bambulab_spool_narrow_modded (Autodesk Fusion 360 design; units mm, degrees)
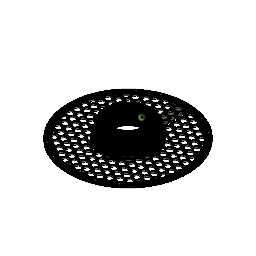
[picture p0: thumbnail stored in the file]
parameter "hole_distance_from_top" = 12.75
parameter "hole_distance_from_sides" = 32
parameter "lattice_thickness" = 3.75
parameter "lattice_diameter" = 10.25
base_mesh_feature "Base Mesh Feature"
convert_mesh "Convert Mesh"
sketch "Sketch1" plane through (0, 0, -13.45) normal (0, 0, 1) x axis (-1, 0, 0)
  line L1 (91.1991, -17.1626) -> (97.9893, -17.84)
  line L2 (90.8249, -19.0441) -> (91.1991, -17.1626)
  line L3 (97.9893, -17.84) -> (90.8249, -19.0441)
  circle C1 centre (94.8184, -14.9969) radius 1.75
  circle C2 centre (94.8205, 15.0016) radius 1.75
  circle C3 centre (60.3969, 74.6167) radius 1.75
  circle C4 centre (-34.4215, 89.6136) radius 1.75
  circle C5 centre (-94.8184, 14.9969) radius 1.75
  circle C6 centre (-60.3969, -74.6167) radius 1.75
  circle C7 centre (34.4215, -89.6136) radius 1.75
  circle C8 centre (34.4185, 89.6178) radius 1.75
  circle C9 centre (-60.402, 74.6162) radius 1.75
  circle C10 centre (-94.8205, -15.0016) radius 1.75
  circle C11 centre (-34.4185, -89.6178) radius 1.75
  circle C12 centre (60.402, -74.6162) radius 1.75
  point P1 (0, 0)
  point P7 (0, 0)
  coincident P1 P7
  dimension "d1" diameter C2 = 3.5
  dimension "d2" diameter C1 = 3.5
  dimension "d4" C-Pattern1-Angle = 360
  dimension "d6" C-Pattern2-Angle = 360
extrude "Extrude1" cut sketch "Sketch1" profile of C3 C4 C6 C7 C8 C9 C11 C12 against normal blind 11
sketch "Sketch2" plane through (0, 0, 0) normal (1, 0, 0) x axis (0, 1, 0)
  line L1 (0, -25) -> (0, 24)
  line L2 (-63, 0) -> (50, 0)
  circle C1 centre (-32, -12.75) radius 1.1
  circle C2 centre (32, -12.75) radius 1.1
  point P2 (-32, -12.75)
  point P3 (32, -12.75)
  vertical L1
  horizontal L2
  dimension "d9" diameter C2 = 2.2
  dimension "d10" diameter C1 = 2.2
  dimension "d11" distance P2 L1 = 32 (= "hole_distance_from_sides")
  dimension "d12" distance P3 L1 = 32 (= "hole_distance_from_sides")
  dimension "d13" distance P3 L2 = 12.75 (= "hole_distance_from_top")
  dimension "d16" distance P2 L2 = 12.75 (= "hole_distance_from_top")
work_plane "WorkPlane1" AlongDistance -61
work_plane "WorkPlane2" AlongDistance -64
work_plane "WorkPlane3" AlongDistance 64
work_plane "WorkPlane4" AlongDistance 65
sketch "Sketch3" plane through (64, 0, 0) normal (1, 0, 0) x axis (0, 1, 0)
  circle C1 centre (-32, -12.75) radius 1.1
  circle C2 centre (32, -12.75) radius 1.1
extrude "Extrude2" cut sketch "Sketch3" against normal blind 57
sketch "Sketch4" plane through (-61, 0, 0) normal (1, 0, 0) x axis (0, 1, 0)
  circle C1 centre (32, -12.75) radius 1.1
  circle C2 centre (-32, -12.75) radius 1.1
extrude "Extrude3" cut sketch "Sketch4" along normal blind 56
sketch "Sketch5" plane through (0, 65, 0) normal (0, 1, 0) x axis (1, 0, 0)
  line L1 (0, 26) -> (0, -23)
  line L2 (-49.4611, 0) -> (56, 0)
  circle C1 centre (32, 12.75) radius 1.1
  circle C2 centre (-32, 12.75) radius 1.1
  point P7 (-32, 12.75)
  point P6 (32, 12.75)
  vertical L1
  horizontal L2
  dimension "d25" diameter C1 = 2.2
  dimension "d26" diameter C2 = 2.2
  dimension "d27" distance L2 P7 = 12.75 (= "hole_distance_from_top")
  dimension "d28" distance L2 P6 = 12.75 (= "hole_distance_from_top")
  dimension "d29" distance L1 P6 = 32 (= "hole_distance_from_sides")
  dimension "d30" distance L1 P7 = 32 (= "hole_distance_from_sides")
extrude "Extrude4" cut sketch "Sketch5" profile of C1 C2 against normal blind 60
sketch "Sketch6" plane through (0, -64, 0) normal (0, 1, 0) x axis (1, 0, 0)
  circle C1 centre (32, 12.75) radius 1.1
  circle C2 centre (-32, 12.75) radius 1.1
extrude "Extrude5" cut sketch "Sketch6" along normal blind 60
sketch "Label" plane through (0, 0, -17.05) normal (0, 0, -1) x axis (1, 0, 0)
  line L1 (-1.2532, -46.0788) -> (-0.6281, -46.0197)
  line L2 (-1.8735, -46.1771) -> (-1.2532, -46.0788)
  line L3 (-2.4873, -46.3143) -> (-1.8735, -46.1771)
  line L4 (-3.0901, -46.4894) -> (-2.4873, -46.3143)
  line L5 (-3.6808, -46.7021) -> (-3.0901, -46.4894)
  line L6 (-0.6281, -46.0197) -> (0, -46.0001)
  line L7 (0.6281, -46.0197) -> (0, -46.0001)
  line L8 (1.2532, -46.0788) -> (0.6281, -46.0197)
  line L9 (1.8735, -46.1771) -> (1.2532, -46.0788)
  line L10 (2.4872, -46.3143) -> (1.8735, -46.1771)
  line L11 (3.0901, -46.4894) -> (2.4872, -46.3143)
  line L12 (3.6808, -46.7021) -> (3.0901, -46.4894)
  line L13 (4.2582, -46.9519) -> (3.6808, -46.7021)
  line L14 (4.8175, -47.2369) -> (4.2582, -46.9519)
  line L15 (5.3579, -47.5565) -> (4.8175, -47.2369)
  line L16 (5.878, -47.91) -> (5.3579, -47.5565)
  line L17 (6.3742, -48.2949) -> (5.878, -47.91)
  line L18 (6.8453, -48.7102) -> (6.3742, -48.2949)
  line L19 (7.2897, -49.1546) -> (6.8453, -48.7102)
  line L20 (7.7051, -49.6258) -> (7.2897, -49.1546)
  line L21 (8.0901, -50.1221) -> (7.7051, -49.6258)
  line L22 (8.4431, -50.6416) -> (8.0901, -50.1221)
  line L23 (8.7631, -51.1825) -> (8.4431, -50.6416)
  line L24 (9.0483, -51.7422) -> (8.7631, -51.1825)
  line L25 (9.2976, -52.3185) -> (9.0483, -51.7422)
  line L26 (9.5106, -52.91) -> (9.2976, -52.3185)
  line L27 (9.6858, -53.5131) -> (9.5106, -52.91)
  line L28 (9.8228, -54.1259) -> (9.6858, -53.5131)
  line L29 (9.9212, -54.7468) -> (9.8228, -54.1259)
  line L30 (9.9802, -55.3716) -> (9.9212, -54.7468)
  line L31 (10, -56) -> (9.9802, -55.3716)
  line L32 (10, -82) -> (10, -56)
  line L33 (-9.2976, -52.3185) -> (-9.0483, -51.7422)
  line L34 (-9.0483, -51.7422) -> (-8.7631, -51.1825)
  line L35 (-8.7631, -51.1825) -> (-8.4431, -50.6416)
  line L36 (-8.4431, -50.6416) -> (-8.0901, -50.1221)
  line L37 (-8.0901, -50.1221) -> (-7.7051, -49.6258)
  line L38 (-7.7051, -49.6258) -> (-7.2897, -49.1546)
  line L39 (-7.2897, -49.1546) -> (-6.8453, -48.7102)
  line L40 (-6.8453, -48.7102) -> (-6.3742, -48.2949)
  line L41 (-6.3742, -48.2949) -> (-5.878, -47.91)
  line L42 (-5.878, -47.91) -> (-5.3579, -47.5565)
  line L43 (-5.3579, -47.5565) -> (-4.8175, -47.2369)
  line L44 (-4.8175, -47.2369) -> (-4.2582, -46.9519)
  line L45 (-4.2582, -46.9519) -> (-3.6808, -46.7021)
  line L46 (-9.5106, -52.91) -> (-9.2976, -52.3185)
  line L47 (-9.6858, -53.5131) -> (-9.5106, -52.91)
  line L48 (-9.8228, -54.1259) -> (-9.6858, -53.5131)
  line L49 (-9.9212, -54.7468) -> (-9.8228, -54.1259)
  line L50 (-9.9802, -55.3716) -> (-9.9212, -54.7468)
  line L51 (-10, -56) -> (-9.9802, -55.3716)
  line L52 (-10, -82) -> (-10, -56)
  line L53 (9.9802, -82.6284) -> (10, -82)
  line L54 (9.9212, -83.2532) -> (9.9802, -82.6284)
  line L55 (9.8228, -83.8741) -> (9.9212, -83.2532)
  line L56 (9.6858, -84.4869) -> (9.8228, -83.8741)
  line L57 (9.5106, -85.09) -> (9.6858, -84.4869)
  line L58 (9.2976, -85.6815) -> (9.5106, -85.09)
  line L59 (9.0483, -86.2578) -> (9.2976, -85.6815)
  line L60 (8.7631, -86.8175) -> (9.0483, -86.2578)
  line L61 (8.4431, -87.3584) -> (8.7631, -86.8175)
  line L62 (8.0901, -87.8779) -> (8.4431, -87.3584)
  line L63 (7.7051, -88.3742) -> (8.0901, -87.8779)
  line L64 (7.2897, -88.8454) -> (7.7051, -88.3742)
  line L65 (6.8453, -89.2898) -> (7.2897, -88.8454)
  line L66 (6.3742, -89.7051) -> (6.8453, -89.2898)
  line L67 (5.878, -90.09) -> (6.3742, -89.7051)
  line L68 (5.3579, -90.4435) -> (5.878, -90.09)
  line L69 (4.8175, -90.7631) -> (5.3579, -90.4435)
  line L70 (4.2582, -91.0481) -> (4.8175, -90.7631)
  line L71 (3.6808, -91.2979) -> (4.2582, -91.0481)
  line L72 (3.0901, -91.5106) -> (3.6808, -91.2979)
  line L73 (2.4872, -91.6857) -> (3.0901, -91.5106)
  line L74 (1.8735, -91.8229) -> (2.4872, -91.6857)
  line L75 (1.2532, -91.9212) -> (1.8735, -91.8229)
  line L76 (0.6281, -91.9803) -> (1.2532, -91.9212)
  line L77 (0, -92) -> (0.6281, -91.9803)
  line L78 (0, -92) -> (-0.6281, -91.9803)
  line L79 (-0.6281, -91.9803) -> (-1.2532, -91.9212)
  line L80 (-1.2532, -91.9212) -> (-1.8735, -91.8229)
  line L81 (-1.8735, -91.8229) -> (-2.4873, -91.6857)
  line L82 (-2.4873, -91.6857) -> (-3.0901, -91.5106)
  line L83 (-3.0901, -91.5106) -> (-3.6808, -91.2979)
  line L84 (-3.6808, -91.2979) -> (-4.2582, -91.0481)
  line L85 (-4.2582, -91.0481) -> (-4.8175, -90.7631)
  line L86 (-4.8175, -90.7631) -> (-5.3579, -90.4435)
  line L87 (-5.3579, -90.4435) -> (-5.878, -90.09)
  line L88 (-5.878, -90.09) -> (-6.3742, -89.7051)
  line L89 (-6.3742, -89.7051) -> (-6.8453, -89.2898)
  line L90 (-6.8453, -89.2898) -> (-7.2897, -88.8454)
  line L91 (-7.2897, -88.8454) -> (-7.7051, -88.3742)
  line L92 (-7.7051, -88.3742) -> (-8.0901, -87.8779)
  line L93 (-8.0901, -87.8779) -> (-8.4431, -87.3584)
  line L94 (-8.4431, -87.3584) -> (-8.7631, -86.8175)
  line L95 (-8.7631, -86.8175) -> (-9.0483, -86.2578)
  line L96 (-9.0483, -86.2578) -> (-9.2976, -85.6815)
  line L97 (-9.2976, -85.6815) -> (-9.5106, -85.09)
  line L98 (-9.5106, -85.09) -> (-9.6858, -84.4869)
  line L99 (-9.6858, -84.4869) -> (-9.8228, -83.8741)
  line L100 (-9.8228, -83.8741) -> (-9.9212, -83.2532)
  line L101 (-9.9212, -83.2532) -> (-9.9802, -82.6284)
  line L102 (-9.9802, -82.6284) -> (-10, -82)
  line L103 (-10.3182, -83.3033) -> (-10.3796, -82.6536)
  line L104 (-10.2159, -83.9491) -> (-10.3182, -83.3033)
  line L105 (-10.0734, -84.5864) -> (-10.2159, -83.9491)
  line L106 (-9.8912, -85.2136) -> (-10.0734, -84.5864)
  line L107 (-9.6697, -85.8289) -> (-9.8912, -85.2136)
  line L108 (-9.4104, -86.4282) -> (-9.6697, -85.8289)
  line L109 (-9.1138, -87.0103) -> (-9.4104, -86.4282)
  line L110 (-8.781, -87.5728) -> (-9.1138, -87.0103)
  line L111 (-8.4139, -88.1131) -> (-8.781, -87.5728)
  line L112 (-8.0135, -88.6293) -> (-8.4139, -88.1131)
  line L113 (-7.5814, -89.1194) -> (-8.0135, -88.6293)
  line L114 (-7.1193, -89.5816) -> (-7.5814, -89.1194)
  line L115 (-6.6293, -90.0135) -> (-7.1193, -89.5816)
  line L116 (-6.1133, -90.4137) -> (-6.6293, -90.0135)
  line L117 (-5.5723, -90.7814) -> (-6.1133, -90.4137)
  line L118 (-5.0103, -91.1138) -> (-5.5723, -90.7814)
  line L119 (-4.4285, -91.4102) -> (-5.0103, -91.1138)
  line L120 (-3.8281, -91.67) -> (-4.4285, -91.4102)
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  dimension "d59" = 0.4
sketch "Sketch7" plane through (0, 0, -14.55) normal (0, 0, 1) x axis (-1, 0, 0)
  line L1 (-2.5625, -4.4384) -> (-5.125, 0)
  line L2 (-5.125, 0) -> (-2.5625, 4.4384)
  line L3 (8.3726, -10.7518) -> (5.8101, -6.3134)
  line L4 (16.0601, -6.3134) -> (13.4976, -10.7518)
  line L5 (13.4976, -10.7518) -> (8.3726, -10.7518)
  line L6 (2.5625, -8.1884) -> (5.125, -12.6268)
  line L7 (5.125, -12.6268) -> (2.5625, -17.0651)
  line L8 (16.0601, -17.0651) -> (16.0601, 10.7518)
  line L9 (2.5625, -17.0651) -> (-2.5625, -17.0651)
  line L10 (5.125, 0) -> (2.5625, -4.4384)
  line L11 (-2.5625, 4.4384) -> (2.5625, 4.4384)
  line L12 (-5.125, -17.0651) -> (16.0601, -17.0651)
  line L13 (-5.125, 10.7518) -> (16.0601, 10.7518)
  line L14 (-37, 0) -> (37, 0)
  line L15 (2.5625, -4.4384) -> (-2.5625, -4.4384)
  line L16 (-2.5625, -17.0651) -> (-5.125, -12.6268)
  line L17 (2.5625, 4.4384) -> (5.125, 0)
  line L18 (13.4976, 10.7518) -> (16.0601, 6.3134)
  line L19 (5.8101, 6.3134) -> (8.3726, 10.7518)
  line L20 (16.0601, 6.3134) -> (13.4976, 1.875)
  line L21 (13.4976, 1.875) -> (8.3726, 1.875)
  line L22 (-2.5625, -8.1884) -> (2.5625, -8.1884)
  line L23 (8.3726, 10.7518) -> (13.4976, 10.7518)
  line L24 (8.3726, -1.875) -> (13.4976, -1.875)
  line L25 (8.3726, 1.875) -> (5.8101, 6.3134)
  line L26 (5.8101, -6.3134) -> (8.3726, -1.875)
  line L27 (13.4976, -1.875) -> (16.0601, -6.3134)
  line L28 (-5.125, -17.0651) -> (-5.125, 10.7518)
  line L29 (0, -45.5) -> (0, 45.5)
  line L30 (-5.125, -12.6268) -> (-2.5625, -8.1884)
  line L31 (-100.8005, -108.8944) -> (-103.363, -113.3327)
  line L32 (-103.363, -113.3327) -> (-108.488, -113.3327)
  line L33 (-108.488, -113.3327) -> (-111.0505, -108.8944)
  line L34 (-111.0505, -108.8944) -> (-108.488, -104.456)
  line L35 (-108.488, -104.456) -> (-103.363, -104.456)
  line L36 (-103.363, -104.456) -> (-100.8005, -108.8944)
  line L37 (-97.5529, -107.0194) -> (-100.1154, -102.581)
  line L38 (-92.4279, -107.0194) -> (-97.5529, -107.0194)
  line L39 (-89.8654, -102.581) -> (-92.4279, -107.0194)
  line L40 (-92.4279, -98.1426) -> (-89.8654, -102.581)
  line L41 (-97.5529, -98.1426) -> (-92.4279, -98.1426)
  line L42 (-100.1154, -102.581) -> (-97.5529, -98.1426)
  line L43 (-100.8005, -96.2676) -> (-103.363, -100.706)
  line L44 (-103.363, -100.706) -> (-108.488, -100.706)
  line L45 (-108.488, -100.706) -> (-111.0505, -96.2676)
  line L46 (-111.0505, -96.2676) -> (-108.488, -91.8292)
  line L47 (-108.488, -91.8292) -> (-103.363, -91.8292)
  line L48 (-103.363, -91.8292) -> (-100.8005, -96.2676)
  line L49 (-97.5529, -94.3926) -> (-100.1154, -89.9542)
  line L50 (-92.4279, -94.3926) -> (-97.5529, -94.3926)
  line L51 (-89.8654, -89.9542) -> (-92.4279, -94.3926)
  line L52 (-92.4279, -85.5158) -> (-89.8654, -89.9542)
  line L53 (-100.1154, -89.9542) -> (-97.5529, -85.5158)
  line L54 (-97.5529, -85.5158) -> (-92.4279, -85.5158)
  line L55 (-79.6154, -108.8944) -> (-82.1779, -113.3327)
  line L56 (-82.1779, -113.3327) -> (-87.3029, -113.3327)
  line L57 (-87.3029, -113.3327) -> (-89.8654, -108.8944)
  line L58 (-89.8654, -108.8944) -> (-87.3029, -104.456)
  line L59 (-87.3029, -104.456) -> (-82.1779, -104.456)
  line L60 (-82.1779, -104.456) -> (-79.6154, -108.8944)
  line L61 (-76.3678, -107.0194) -> (-78.9303, -102.581)
  line L62 (-71.2428, -107.0194) -> (-76.3678, -107.0194)
  line L63 (-68.6803, -102.581) -> (-71.2428, -107.0194)
  line L64 (-71.2428, -98.1426) -> (-68.6803, -102.581)
  line L65 (-76.3678, -98.1426) -> (-71.2428, -98.1426)
  line L66 (-78.9303, -102.581) -> (-76.3678, -98.1426)
  line L67 (-79.6154, -96.2676) -> (-82.1779, -100.706)
  line L68 (-82.1779, -100.706) -> (-87.3029, -100.706)
  line L69 (-87.3029, -100.706) -> (-89.8654, -96.2676)
  line L70 (-89.8654, -96.2676) -> (-87.3029, -91.8292)
  line L71 (-87.3029, -91.8292) -> (-82.1779, -91.8292)
  line L72 (-82.1779, -91.8292) -> (-79.6154, -96.2676)
  line L73 (-76.3678, -94.3926) -> (-78.9303, -89.9542)
  line L74 (-71.2428, -94.3926) -> (-76.3678, -94.3926)
  line L75 (-68.6803, -89.9542) -> (-71.2428, -94.3926)
  line L76 (-71.2428, -85.5158) -> (-68.6803, -89.9542)
  line L77 (-78.9303, -89.9542) -> (-76.3678, -85.5158)
  line L78 (-76.3678, -85.5158) -> (-71.2428, -85.5158)
  line L79 (-58.4303, -108.8944) -> (-60.9928, -113.3327)
  line L80 (-60.9928, -113.3327) -> (-66.1178, -113.3327)
  line L81 (-66.1178, -113.3327) -> (-68.6803, -108.8944)
  line L82 (-68.6803, -108.8944) -> (-66.1178, -104.456)
  line L83 (-66.1178, -104.456) -> (-60.9928, -104.456)
  line L84 (-60.9928, -104.456) -> (-58.4303, -108.8944)
  line L85 (-55.1827, -107.0194) -> (-57.7452, -102.581)
  line L86 (-50.0577, -107.0194) -> (-55.1827, -107.0194)
  line L87 (-47.4952, -102.581) -> (-50.0577, -107.0194)
  line L88 (-50.0577, -98.1426) -> (-47.4952, -102.581)
  line L89 (-55.1827, -98.1426) -> (-50.0577, -98.1426)
  line L90 (-57.7452, -102.581) -> (-55.1827, -98.1426)
  line L91 (-58.4303, -96.2676) -> (-60.9928, -100.706)
  line L92 (-60.9928, -100.706) -> (-66.1178, -100.706)
  line L93 (-66.1178, -100.706) -> (-68.6803, -96.2676)
  line L94 (-68.6803, -96.2676) -> (-66.1178, -91.8292)
  line L95 (-66.1178, -91.8292) -> (-60.9928, -91.8292)
  line L96 (-60.9928, -91.8292) -> (-58.4303, -96.2676)
  line L97 (-55.1827, -94.3926) -> (-57.7452, -89.9542)
  line L98 (-50.0577, -94.3926) -> (-55.1827, -94.3926)
  line L99 (-47.4952, -89.9542) -> (-50.0577, -94.3926)
  line L100 (-50.0577, -85.5158) -> (-47.4952, -89.9542)
  line L101 (-57.7452, -89.9542) -> (-55.1827, -85.5158)
  line L102 (-55.1827, -85.5158) -> (-50.0577, -85.5158)
  line L103 (-37.2452, -108.8944) -> (-39.8077, -113.3327)
  line L104 (-39.8077, -113.3327) -> (-44.9327, -113.3327)
  line L105 (-44.9327, -113.3327) -> (-47.4952, -108.8944)
  line L106 (-47.4952, -108.8944) -> (-44.9327, -104.456)
  line L107 (-44.9327, -104.456) -> (-39.8077, -104.456)
  line L108 (-39.8077, -104.456) -> (-37.2452, -108.8944)
  line L109 (-33.9976, -107.0194) -> (-36.5601, -102.581)
  line L110 (-28.8726, -107.0194) -> (-33.9976, -107.0194)
  line L111 (-26.3101, -102.581) -> (-28.8726, -107.0194)
  line L112 (-28.8726, -98.1426) -> (-26.3101, -102.581)
  line L113 (-33.9976, -98.1426) -> (-28.8726, -98.1426)
  line L114 (-36.5601, -102.581) -> (-33.9976, -98.1426)
  line L115 (-37.2452, -96.2676) -> (-39.8077, -100.706)
  line L116 (-39.8077, -100.706) -> (-44.9327, -100.706)
  line L117 (-44.9327, -100.706) -> (-47.4952, -96.2676)
  line L118 (-47.4952, -96.2676) -> (-44.9327, -91.8292)
  line L119 (-44.9327, -91.8292) -> (-39.8077, -91.8292)
  line L120 (-39.8077, -91.8292) -> (-37.2452, -96.2676)
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  point P1 (0, 0)
  point P2 (0, 0)
  point P3 (0, 0)
  point P4 (0, 0)
  point P5 (0, 0)
  point P41 (0, 0)
  point P6 (0, 0)
  point P7 (0, 0)
  point P14 (0, 0)
  point P21 (0, -12.6268)
  point P10 (-5.125, 0)
  point P27 (16.0601, -6.3134)
  point P43 (16.0601, -17.0651)
  point P44 (-5.125, -17.0651)
  point P40 (-5.125, 10.7518)
  point P42 (16.0601, 10.7518)
  point P2661 (0, 0)
  point P13 (5.125, 0)
  point P8 (2.5625, 4.4384)
  point P11 (-2.5625, -4.4384)
  point P16 (5.125, -12.6268)
  point P19 (-5.125, -12.6268)
  point P15 (2.5625, -17.0651)
  point P18 (-2.5625, -8.1884)
  point P30 (5.8101, -6.3134)
  point P33 (16.0601, 6.3134)
  point P36 (5.8101, 6.3134)
  coincident P1 P2
  coincident P2 P3
  coincident P1 P4
  coincident P5 P41
  coincident P6 P41
  coincident P7 P41
  coincident P6 P14
  vertical L29
  horizontal L14
  coincident P41 L29
  midpoint P5 L14
  midpoint P41 L29
  coincident P21 L29
  parallel L14 L15
  parallel L5 L14
  parallel L14 L21
  vertical L28
  vertical L8
  coincident P10 L28
  coincident P27 L8
  perpendicular L8 L13
  horizontal L12
  collinear L13 L23
  collinear L9 L12
  coincident P43 L8
  coincident P44 L28
  coincident P40 L13
  coincident P42 L8
  coincident P2 P2661
  dimension "d35" diameter = 183.4
  dimension "d38" diameter = 179.65 (= "183.4 mm - lattice_thickness")
  dimension "d63" distance P10 P13 = 10.25 (= "lattice_diameter")
  dimension "d64" distance P8 P11 = 10.25 (= "lattice_diameter")
  dimension "d65" distance P16 P19 = 10.25 (= "lattice_diameter")
  dimension "d66" distance P15 P18 = 10.25 (= "lattice_diameter")
  dimension "d67" distance L15 L22 = 3.75 (= "lattice_thickness")
  dimension "d68" distance P27 P30 = 10.25 (= "lattice_diameter")
  dimension "d69" distance L10 L26 = 3.75 (= "lattice_thickness")
  dimension "d70" distance L3 L6 = 3.75 (= "lattice_thickness")
  dimension "d71" distance P33 P36 = 10.25 (= "lattice_diameter")
  dimension "d72" distance L21 L24 = 3.75 (= "lattice_thickness")
  dimension "d73" distance L17 L25 = 3.75 (= "lattice_thickness")
  dimension "d74" distance P43 P44 = 21.1851
  dimension "d75" distance P42 P43 = 27.8169
  dimension "d56" diameter = 89
  dimension "d54" R-Pattern1-uDistance = 21.1851
  dimension "d55" R-Pattern1-vDistance = 24.0669 (= "27.816899 mm - lattice_thickness")
extrude "Extrude6" cut sketch "Sketch7" distance 30
extrude "Extrude7" add sketch "Label" profile of L1 L2 L3 L4 L5 L6 L7 L8 L9 L10 L11 L12 L13 L14 L15 L16 L17 L18 L19 L20 L21 L22 L23 L24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 against normal blind 0.4
sketch "Sketch13" plane through (-3.8901, 27.2222, 0) normal (0.1415, -0.9899, 0) x axis (0.9899, 0.1415, 0)
  line L1 (3.3587, 0) -> (-3.6413, 0)
  line L2 (-0.1413, 3.5) -> (-3.6413, 0)
  line L3 (3.3587, 0) -> (-0.1413, 3.5)
  line L4 (-0.1413, 0) -> (-0.1413, 3.5)
  point P2 (-0.1413, 0)
  point P6 (-0.1413, 0)
  point P5 (-0.1413, 3.5)
  horizontal L1
  coincident P2 P6
  coincident P2 L1
  equal L2 L3
  perpendicular L1 L4
  dimension "d92" distance P5 P6 = 3.5
  dimension "d93" angle L2 L3 = 90
sketch "Sketch15" plane through (3.8901, -27.2222, 0) normal (-0.1415, 0.9899, 0) x axis (-0.9899, -0.1415, 0)
  line L1 (-0.1438, 3.5) -> (3.3562, 0)
  line L2 (-3.6438, 0) -> (-0.1438, 3.5)
  line L3 (-3.6438, 0) -> (3.3562, 0)
extrude "Extrude10" cut sketch "Sketch13" profile of L1 L2 L3 along normal blind 5 and against normal blind 0.5
chamfer "Chamfer1" distance 0.5 Rotate Angle 45
extrude "Extrude11" cut sketch "Sketch15" along normal blind 5 and against normal blind 0.5
chamfer "Chamfer2" distance 0.5 Rotate Angle 45
named bodies: "bambulab_spool_narrow"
